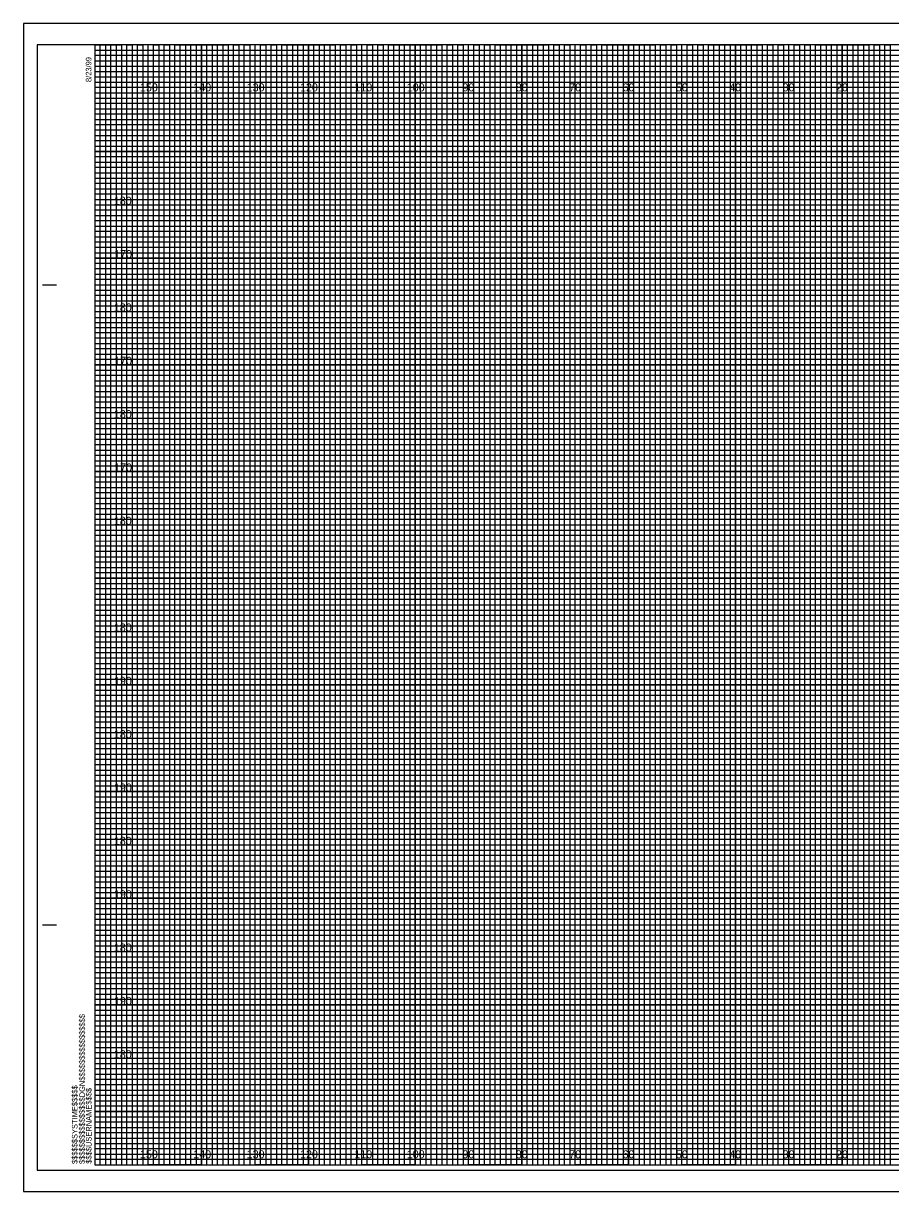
# Model space of a CAD drawing. Extents: x -13 to 323, y 215 to 434.
# Drawn here: x -13.4 to 149.1, y 215 to 434 of the extents above; entities that cross this region are included whole.
import ezdxf

# ---------------------------------------------------------------- set-up
doc = ezdxf.new("R2010")
doc.units = 0
for name, color, linetype in [('Exist Cross Section Cell', 7, 'Continuous'), ('Exist XS Center Line Elevation Label', 7, 'Continuous'), ('Exist XS Ground Line', 7, 'Continuous'), ('Prop CMT Pvmt Course 1', 7, 'Continuous'), ('Prop CMT Pvmt Course 3', 7, 'Continuous'), ('Prop CMT Pvmt Surface', 7, 'Continuous'), ('Prop CMT Pvmt Surface Shoulder', 7, 'Continuous'), ('Prop CMT Shld Paved Course 1', 7, 'Continuous'), ('Prop CMT Shld Paved Course 2', 7, 'Continuous'), ('Prop CMT Subgrade Earthwork', 7, 'Continuous'), ('Scratch_Level_2', 7, 'Continuous')]:
    doc.layers.add(name, color=color, linetype=linetype)

msp = doc.modelspace()

# ---------------------------------------------------------------- linework, layer by layer
at = {"layer": 'Exist XS Center Line Elevation Label'}
for points in [[(0, 430), (5, 430), (5, 220), (15, 220), (15, 430), (25, 430), (25, 220), (35, 220), (35, 430), (45, 430), (45, 220), (55, 220), (55, 430), (65, 430), (65, 220), (75, 220), (75, 430), (85, 430), (85, 220), (95, 220), (95, 430), (105, 430), (105, 220), (115, 220), (115, 430), (125, 430), (125, 220), (135, 220), (135, 430), (145, 430), (145, 220), (155, 220)], [(0, 425), (275, 425)], [(0, 405), (320, 405), (320, 415), (0, 415)], [(0, 385), (320, 385), (320, 395), (0, 395)], [(0, 365), (320, 365), (320, 375), (0, 375)], [(0, 345), (320, 345), (320, 355), (0, 355)], [(0, 325), (320, 325), (320, 335), (0, 335)], [(0, 305), (320, 305), (320, 315), (0, 315)], [(0, 285), (320, 285), (320, 295), (0, 295)], [(0, 265), (320, 265), (320, 275), (0, 275)], [(0, 245), (320, 245), (320, 255), (0, 255)], [(0, 225), (320, 225), (320, 235), (0, 235)]]:
    msp.add_lwpolyline(points, dxfattribs=at)
at = {"layer": 'Exist XS Ground Line'}
for p, q in [((10, 430), (0, 430)), ((10, 220), (10, 430)), ((30, 430), (20, 430)), ((20, 430), (20, 220)), ((30, 220), (30, 430)), ((50, 430), (40, 430)), ((40, 430), (40, 220)), ((50, 220), (50, 430)), ((70, 430), (60, 430)), ((60, 430), (60, 220)), ((70, 220), (70, 430)), ((90, 430), (80, 430)), ((80, 430), (80, 220)), ((90, 220), (90, 430)), ((110, 430), (100, 430)), ((100, 430), (100, 220)), ((110, 220), (110, 430)), ((130, 430), (120, 430)), ((120, 430), (120, 220)), ((130, 220), (130, 430)), ((150, 430), (140, 430)), ((140, 430), (140, 220)), ((20, 220), (10, 220)), ((40, 220), (30, 220)), ((60, 220), (50, 220)), ((80, 220), (70, 220)), ((100, 220), (90, 220)), ((120, 220), (110, 220)), ((140, 220), (130, 220))]:
    msp.add_line(p, q, dxfattribs=at)
for points in [[(0, 420), (320, 420), (320, 410), (0, 410)], [(0, 400), (320, 400), (320, 390), (0, 390)], [(0, 380), (320, 380), (320, 370), (0, 370)], [(0, 360), (320, 360), (320, 350), (0, 350)], [(0, 340), (320, 340), (320, 330), (0, 330)], [(0, 320), (320, 320), (320, 310), (0, 310)], [(0, 300), (320, 300), (320, 290), (0, 290)], [(0, 280), (320, 280), (320, 270), (0, 270)], [(0, 260), (320, 260), (320, 250), (0, 250)], [(0, 240), (320, 240), (320, 230), (0, 230)]]:
    msp.add_lwpolyline(points, dxfattribs=at)
at = {"layer": 'Prop CMT Pvmt Course 1'}
for p, q in [((323.3, 434), (-13.4, 434)), ((-13.4, 434), (-13.4, 215)), ((-13.4, 215), (323.3, 215))]:
    msp.add_line(p, q, dxfattribs=at)
at = {"layer": 'Prop CMT Pvmt Surface'}
msp.add_lwpolyline([(-10.8, 219), (322.4, 219), (322.4, 430), (-10.8, 430)], close=True, dxfattribs=at)
at = {"layer": 'Prop CMT Pvmt Surface Shoulder'}
for p, q in [((10, 220), (10, 430)), ((20, 220), (20, 430)), ((30, 220), (30, 430)), ((40, 220), (40, 430)), ((50, 220), (50, 430)), ((60, 220), (60, 430)), ((70, 220), (70, 430)), ((80, 220), (80, 430)), ((90, 220), (90, 430)), ((100, 220), (100, 430)), ((110, 220), (110, 430)), ((120, 220), (120, 430)), ((130, 220), (130, 430)), ((140, 220), (140, 430)), ((0, 420), (320, 420)), ((0, 410), (320, 410)), ((0, 400), (320, 400)), ((0, 390), (320, 390)), ((0, 380), (320, 380)), ((0, 370), (320, 370)), ((0, 360), (320, 360)), ((0, 350), (320, 350)), ((0, 340), (320, 340)), ((0, 330), (320, 330)), ((0, 320), (320, 320)), ((0, 310), (320, 310)), ((0, 300), (320, 300)), ((0, 290), (320, 290)), ((0, 280), (320, 280)), ((0, 270), (320, 270)), ((0, 260), (320, 260)), ((0, 250), (320, 250)), ((0, 240), (320, 240)), ((0, 230), (320, 230))]:
    msp.add_line(p, q, dxfattribs=at)
at = {"layer": 'Prop CMT Shld Paved Course 1'}
for p, q in [((-9.8, 385), (-7.3, 385)), ((-9.7, 385), (-7.2, 385)), ((-9.8, 265), (-7.3, 265)), ((-9.7, 265), (-7.2, 265)), ((0, 220), (0, 220)), ((0, 220), (0, 220)), ((0, 220), (0, 220)), ((0, 220), (0, 220)), ((0, 220), (0, 220)), ((0, 220), (0, 220)), ((0, 220), (0, 220))]:
    msp.add_line(p, q, dxfattribs=at)
msp.add_lwpolyline([(320, 430), (0, 430), (0, 220), (320, 220)], close=True, dxfattribs=at)
at = {"layer": 'Prop CMT Shld Paved Course 2'}
for points in [[(0, 220), (1, 220), (1, 430), (2, 430), (2, 220)], [(2, 220), (3, 220), (3, 430), (4, 430), (4, 220)], [(5, 220), (6, 220), (6, 430), (7, 430), (7, 220)], [(7, 220), (8, 220), (8, 430), (9, 430), (9, 220)], [(10, 220), (11, 220), (11, 430), (12, 430), (12, 220)], [(12, 220), (13, 220), (13, 430), (14, 430), (14, 220)], [(15, 220), (16, 220), (16, 430), (17, 430), (17, 220)], [(17, 220), (18, 220), (18, 430), (19, 430), (19, 220)], [(20, 220), (21, 220), (21, 430), (22, 430), (22, 220)], [(22, 220), (23, 220), (23, 430), (24, 430), (24, 220)], [(25, 220), (26, 220), (26, 430), (27, 430), (27, 220)], [(27, 220), (28, 220), (28, 430), (29, 430), (29, 220)], [(30, 220), (31, 220), (31, 430), (32, 430), (32, 220)], [(32, 220), (33, 220), (33, 430), (34, 430), (34, 220)], [(35, 220), (36, 220), (36, 430), (37, 430), (37, 220)], [(37, 220), (38, 220), (38, 430), (39, 430), (39, 220)], [(40, 220), (41, 220), (41, 430), (42, 430), (42, 220)], [(42, 220), (43, 220), (43, 430), (44, 430), (44, 220)], [(45, 220), (46, 220), (46, 430), (47, 430), (47, 220)], [(47, 220), (48, 220), (48, 430), (49, 430), (49, 220)], [(50, 220), (51, 220), (51, 430), (52, 430), (52, 220)], [(52, 220), (53, 220), (53, 430), (54, 430), (54, 220)], [(55, 220), (56, 220), (56, 430), (57, 430), (57, 220)], [(57, 220), (58, 220), (58, 430), (59, 430), (59, 220)], [(60, 220), (61, 220), (61, 430), (62, 430), (62, 220)], [(62, 220), (63, 220), (63, 430), (64, 430), (64, 220)], [(65, 220), (66, 220), (66, 430), (67, 430), (67, 220)], [(67, 220), (68, 220), (68, 430), (69, 430), (69, 220)], [(70, 220), (71, 220), (71, 430), (72, 430), (72, 220)], [(72, 220), (73, 220), (73, 430), (74, 430), (74, 220)], [(75, 220), (76, 220), (76, 430), (77, 430), (77, 220)], [(77, 220), (78, 220), (78, 430), (79, 430), (79, 220)], [(80, 220), (81, 220), (81, 430), (82, 430), (82, 220)], [(82, 220), (83, 220), (83, 430), (84, 430), (84, 220)], [(85, 220), (86, 220), (86, 430), (87, 430), (87, 220)], [(87, 220), (88, 220), (88, 430), (89, 430), (89, 220)], [(90, 220), (91, 220), (91, 430), (92, 430), (92, 220)], [(92, 220), (93, 220), (93, 430), (94, 430), (94, 220)], [(95, 220), (96, 220), (96, 430), (97, 430), (97, 220)], [(97, 220), (98, 220), (98, 430), (99, 430), (99, 220)], [(100, 220), (101, 220), (101, 430), (102, 430), (102, 220)], [(102, 220), (103, 220), (103, 430), (104, 430), (104, 220)], [(105, 220), (106, 220), (106, 430), (107, 430), (107, 220)], [(107, 220), (108, 220), (108, 430), (109, 430), (109, 220)], [(110, 220), (111, 220), (111, 430), (112, 430), (112, 220)], [(112, 220), (113, 220), (113, 430), (114, 430), (114, 220)], [(115, 220), (116, 220), (116, 430), (117, 430), (117, 220)], [(117, 220), (118, 220), (118, 430), (119, 430), (119, 220)], [(120, 220), (121, 220), (121, 430), (122, 430), (122, 220)], [(122, 220), (123, 220), (123, 430), (124, 430), (124, 220)], [(125, 220), (126, 220), (126, 430), (127, 430), (127, 220)], [(127, 220), (128, 220), (128, 430), (129, 430), (129, 220)], [(130, 220), (131, 220), (131, 430), (132, 430), (132, 220)], [(132, 220), (133, 220), (133, 430), (134, 430), (134, 220)], [(135, 220), (136, 220), (136, 430), (137, 430), (137, 220)], [(137, 220), (138, 220), (138, 430), (139, 430), (139, 220)], [(140, 220), (141, 220), (141, 430), (142, 430), (142, 220)], [(142, 220), (143, 220), (143, 430), (144, 430), (144, 220)], [(145, 220), (146, 220), (146, 430), (147, 430), (147, 220)], [(147, 220), (148, 220), (148, 430), (149, 430), (149, 220)]]:
    msp.add_lwpolyline(points, dxfattribs=at)
at = {"layer": 'Prop CMT Subgrade Earthwork'}
msp.add_lwpolyline([(-13.4, 215), (323.3, 215), (323.3, 434), (-13.4, 434)], close=True, dxfattribs=at)
at = {"layer": 'Scratch_Level_2'}
for p, q in [((0, 429), (260, 429)), ((260, 427.98), (0, 427.98)), ((0, 427.98), (0, 427)), ((0, 427), (260, 427)), ((260, 425.89), (0, 425.89)), ((0, 425.89), (0, 424)), ((0, 424), (320, 424))]:
    msp.add_line(p, q, dxfattribs=at)
for points in [[(0, 423), (270, 423), (320, 423), (320, 422), (0, 422)], [(0, 421), (320, 421), (320, 419), (0, 419)], [(0, 418), (320, 418), (320, 417), (0, 416.98)], [(0, 416), (320, 416), (320, 414), (0, 414)], [(0, 413), (320, 413), (320, 412), (0, 412)], [(0, 411), (320, 411), (320, 409), (0, 409)], [(0, 408), (320, 408), (320, 407), (0, 407)], [(0, 406), (320, 406), (320, 404), (0, 404)], [(0, 403), (320, 403), (320, 402), (0, 402)], [(0, 401), (320, 401), (320, 399), (0, 399)], [(0, 398), (320, 398), (320, 397), (0, 397)], [(0, 396), (320, 396), (320, 393.95), (320, 393), (320, 392), (0, 392)], [(0, 394), (320, 394), (320, 393), (0, 393)], [(0, 391), (320, 391), (320, 389), (0, 389.03)], [(0, 389.03), (320, 389), (320, 388), (0, 388)], [(0, 387), (320, 387), (320, 386), (0, 386)], [(0, 384), (320, 384), (320, 383), (0, 383)], [(0, 382), (320, 382), (320, 381), (0, 381)], [(-0.07, 378.89), (320, 378.89), (320, 377.88), (-0.07, 377.88)], [(0, 377), (320, 377), (320, 376), (0, 376)], [(0, 374), (320, 374), (320, 373), (0, 373)], [(0, 372), (320, 372), (320, 371), (0, 371)], [(0, 369), (320, 369), (320, 368), (0, 368)], [(0, 367), (320, 367), (320, 366), (0, 366)], [(0, 364), (320, 364), (320, 363), (0, 363)], [(0, 362), (320, 362), (320, 361), (0, 361)], [(0, 359), (320, 359), (319.99, 357.98), (0, 358)], [(0, 357), (320, 357), (320, 356), (0, 356)], [(0, 354), (320, 354), (320, 353), (0, 353)], [(0, 352), (320, 352), (320, 351), (0, 351)], [(0, 349), (320, 349), (320, 348), (0, 348)], [(0, 347), (320, 347), (320, 346), (0, 346)], [(0, 344), (320, 344), (320, 343), (0, 343)], [(0, 342), (320, 342), (320, 341), (0, 341)], [(0, 339), (320, 339), (320, 338), (0, 338)], [(0, 336.99), (320.07, 336.91), (320, 336), (0, 336)], [(0, 334), (320, 334), (320, 333), (0, 333)], [(0, 332), (320, 332), (320, 331), (0, 331)], [(0, 329), (320, 329), (320, 328), (0, 328)], [(0, 327), (320, 327), (320, 326), (0, 326)], [(0, 324), (320, 324), (320, 323), (0, 323)], [(0, 322), (320, 322), (320, 321), (0, 321)], [(0, 319), (320, 319), (320, 318), (0, 318)], [(0, 317), (320, 317), (320, 316), (0, 316)], [(0, 314), (320, 314), (320, 313), (0, 313)], [(0, 312), (320, 312), (320, 311), (0, 311)], [(0, 309), (320, 309), (320, 308), (0, 308)], [(0, 307), (320, 307), (320, 306), (0, 306)], [(0, 304), (320, 304), (320, 303), (0, 303)], [(0, 302), (320, 302), (320, 301), (0, 301)], [(0, 299), (320, 299), (319.99, 297.98), (0, 298)], [(0, 297), (320, 297), (320, 296), (0, 296)], [(0, 294), (320, 294), (320, 293), (0, 293)], [(0, 292), (320, 292), (320, 291), (0, 291)], [(0, 289), (320, 289), (320, 288), (0, 288)], [(0, 287), (320, 287), (320, 286), (0, 286)], [(0, 284), (320, 284), (320, 283), (0, 283)], [(0, 282), (320, 282), (320, 281), (0, 281)], [(0, 279), (320, 279), (320, 278), (0, 278)], [(0, 276.99), (320.07, 276.91), (320, 276), (0, 276)], [(0, 274), (320, 274), (320, 273), (0, 273)], [(0, 272), (320, 272), (320, 271), (0, 271)], [(0, 269), (320, 269), (320, 268), (0, 268)], [(0, 267), (320, 267), (320, 266), (0, 266)], [(0, 264), (320, 264), (320, 263), (0, 263)], [(0, 262), (320, 262), (320, 261), (0, 261)], [(0, 259), (320, 259), (320, 258), (0, 258)], [(0, 257), (320, 257), (320, 256), (0, 256)], [(0, 254), (320, 254), (320, 253), (0, 253)], [(0, 252), (320, 252), (320, 251), (0, 251)], [(0, 249), (320, 249), (320, 248), (0, 248)], [(0, 247), (320, 247), (320, 246), (0, 246)], [(0, 244), (320, 244), (320, 243), (0, 243)], [(0, 242), (320, 242), (320, 241), (0, 241)], [(0, 239), (320, 239), (320, 238), (0, 238)], [(0, 237), (320, 237), (320, 236), (0, 236)], [(0, 234), (320, 234), (320, 233), (0, 233)], [(0, 232), (320, 232), (320, 231), (0, 231)], [(0, 229), (320, 229), (320, 228), (0, 228)], [(0, 227), (320, 227), (320, 226), (0, 226)], [(0, 224), (320, 224), (320, 223), (0, 223)], [(0, 222), (320, 222), (320, 221), (0, 221)]]:
    msp.add_lwpolyline(points, dxfattribs=at)

# ---------------------------------------------------------------- texts
at = {"layer": 'Exist Cross Section Cell'}
for s, p in [('150', (8.44, 421.25)), ('140', (18.44, 421.25)), ('130', (28.44, 421.25)), ('120', (38.44, 421.25)), ('110', (48.62, 421.25)), ('100', (58.44, 421.25)), ('90', (68.86, 421.25)), ('80', (78.86, 421.25)), ('70', (88.86, 421.25)), ('60', (98.86, 421.25)), ('50', (108.86, 421.25)), ('40', (118.86, 421.25)), ('30', (128.86, 421.25)), ('20', (138.86, 421.25)), ('150', (8.44, 221.25)), ('140', (18.44, 221.25)), ('130', (28.44, 221.25)), ('120', (38.44, 221.25)), ('110', (48.62, 221.25)), ('100', (58.44, 221.25)), ('90', (68.86, 221.25)), ('80', (78.86, 221.25)), ('70', (88.86, 221.25)), ('60', (98.86, 221.25)), ('50', (108.86, 221.25)), ('40', (118.86, 221.25)), ('30', (128.86, 221.25)), ('20', (138.86, 221.25))]:
    msp.add_text(s, height=1.5, dxfattribs=at).set_placement(p)
at = {"layer": 'Prop CMT Pvmt Course 3'}
for s, p in [('180', (3.55, 400)), ('170', (3.61, 390)), ('180', (3.55, 380)), ('170', (3.61, 370)), ('180', (3.55, 360)), ('170', (3.61, 350)), ('180', (3.55, 340)), ('180', (3.55, 320)), ('190', (3.57, 310)), ('180', (3.55, 300)), ('190', (3.57, 290)), ('180', (3.55, 280)), ('190', (3.57, 270)), ('180', (3.55, 260)), ('190', (3.57, 250)), ('180', (3.55, 240))]:
    msp.add_text(s, height=1.5, dxfattribs=at).set_placement(p)
at = {"layer": 'Prop CMT Shld Paved Course 1'}
for s, p in [('8/23/99', (-0.65, 423)), ('$$$$$$$$$$$$$$$$DGN$$$$$$$$$$$$$$$$', (-1.88, 220.18)), ('$$$$$$SYSTIME$$$$$', (-3.26, 220.18)), ('$$$$USERNAME$$$$', (-0.62, 220.23))]:
    msp.add_text(s, height=1.05, rotation=90, dxfattribs=at).set_placement(p)

doc.saveas('drawing.dxf')
